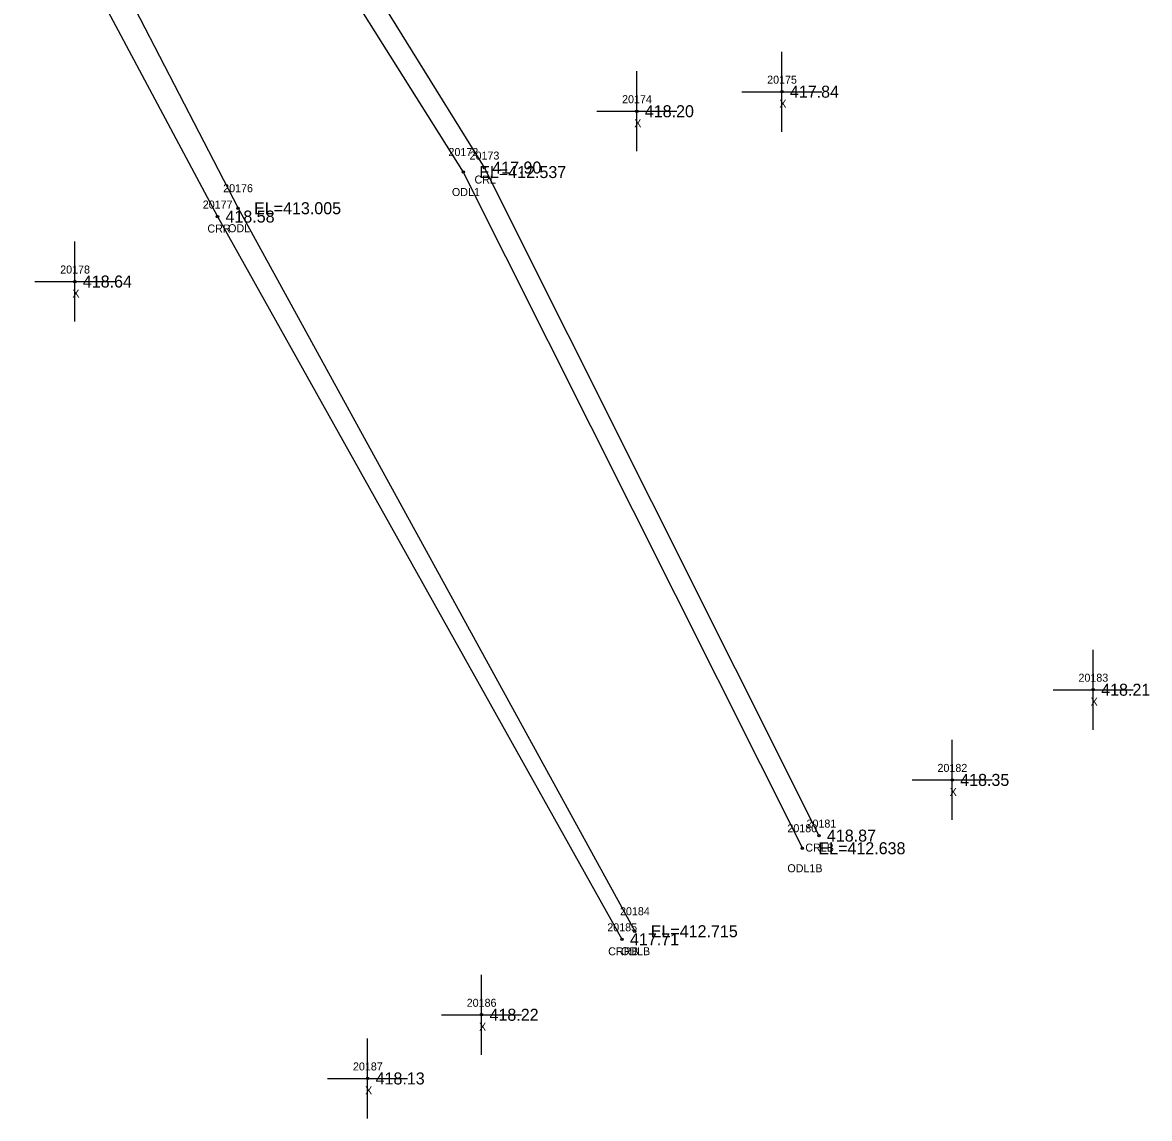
# Model space of a CAD drawing. Extents: x 1613184 to 1614731, y 770859 to 771868.
# Drawn here: x 1614039.7 to 1614180.6, y 770858.6 to 770995.6 of the extents above; entities that cross this region are included whole.
import ezdxf

# ---------------------------------------------------------------- set-up
doc = ezdxf.new("R2010")
doc.units = 0
for name, color, linetype in [('RD_EX_H2O', 7, 'Continuous'), ('RD_EX_H2O_txCode', 7, 'Continuous'), ('RD_EX_Misc', 7, 'Continuous'), ('RD_EX_Misc_txCode', 7, 'Continuous'), ('RD_EX_TX_H2O_ELEV', 7, 'Continuous'), ('RD_EX_TX_Misc_ELEV', 7, 'Continuous'), ('RD_SMD_Locator', 7, 'Continuous')]:
    doc.layers.add(name, color=color, linetype=linetype)

msp = doc.modelspace()

# ---------------------------------------------------------------- linework, layer by layer
at = {"layer": 'RD_EX_H2O'}
for points in [[(1613914.71, 771327.05), (1613912.94, 771270.2), (1613909.29, 771229.14), (1613936.32, 771173.24), (1613961.59, 771155.78), (1613976.99, 771153.11), (1613987.89, 771138.66), (1614016.07, 771061.15), (1614064.07, 770971.34), (1614114.62, 770881.02)], [(1613918.3, 771327.47), (1613915.56, 771269.65), (1613912.54, 771229.9), (1613937.35, 771175.56), (1613962.55, 771156.92), (1613978.15, 771155.33), (1613989.65, 771139.95), (1614019.92, 771062.64), (1614066.64, 770972.38), (1614116.22, 770882.03)], [(1613939.34, 771325.64), (1613936.19, 771267.33), (1613931.54, 771235.48), (1613951.01, 771188.77), (1613971.87, 771179.88), (1613985.53, 771176.18), (1614010.21, 771154.12), (1614036.29, 771069.78), (1614094.78, 770976.9), (1614137.18, 770892.4)], [(1613940.63, 771325.49), (1613938.42, 771267.33), (1613934.3, 771235.92), (1613956.7, 771194.52), (1613973.34, 771185.91), (1613987.6, 771179.19), (1614011.07, 771155.33), (1614038.76, 771071.93), (1614097.41, 770977.46), (1614139.24, 770893.98)]]:
    msp.add_lwpolyline(points, dxfattribs=at)
at = {"layer": 'RD_EX_Misc'}
for p, q in [((1614134.61, 770981.94), (1614134.61, 770991.94)), ((1614116.48, 770979.5), (1614116.48, 770989.5)), ((1614129.61, 770986.94), (1614139.61, 770986.94)), ((1614111.48, 770984.5), (1614121.48, 770984.5)), ((1614046.24, 770958.22), (1614046.24, 770968.22)), ((1614041.24, 770963.22), (1614051.24, 770963.22)), ((1614173.52, 770907.21), (1614173.52, 770917.21)), ((1614168.52, 770912.21), (1614178.52, 770912.21)), ((1614155.9, 770895.94), (1614155.9, 770905.94)), ((1614150.9, 770900.94), (1614160.9, 770900.94)), ((1614097.07, 770866.59), (1614097.07, 770876.59)), ((1614092.07, 770871.59), (1614102.07, 770871.59)), ((1614082.83, 770858.63), (1614082.83, 770868.63)), ((1614077.83, 770863.63), (1614087.83, 770863.63))]:
    msp.add_line(p, q, dxfattribs=at)
at = {"layer": 'RD_SMD_Locator'}
for centre in [(1614134.61, 770986.94), (1614116.48, 770984.5), (1614094.78, 770976.9), (1614097.41, 770977.46), (1614064.07, 770971.34), (1614066.64, 770972.38), (1614046.24, 770963.22), (1614173.52, 770912.21), (1614155.9, 770900.94), (1614139.24, 770893.98), (1614137.18, 770892.4), (1614116.22, 770882.03), (1614114.62, 770881.02), (1614097.07, 770871.59), (1614082.83, 770863.63)]:
    msp.add_circle(centre, 0.15, dxfattribs=at)

# ---------------------------------------------------------------- texts
at = {"layer": 'RD_EX_H2O_txCode'}
for s, p in [('20172', (1614092.94, 770978.9)), ('20173', (1614095.58, 770978.46)), ('CRL', (1614096.19, 770975.46)), ('20176', (1614064.78, 770974.38)), ('ODL1', (1614093.37, 770973.9)), ('20177', (1614062.23, 770972.34)), ('CRR', (1614062.81, 770969.34)), ('ODL', (1614065.4, 770969.38)), ('20180', (1614135.3, 770894.4)), ('20181', (1614137.69, 770894.98)), ('CRLB', (1614137.54, 770891.98)), ('ODL1B', (1614135.3, 770889.4)), ('20184', (1614114.38, 770884.03)), ('20185', (1614112.79, 770882.02)), ('CRRB', (1614112.9, 770879.02)), ('ODLB', (1614114.5, 770879.03))]:
    msp.add_text(s, height=1, dxfattribs=at).set_placement(p)
at = {"layer": 'RD_EX_Misc_txCode'}
for s, p in [('20175', (1614132.77, 770987.94)), ('20174', (1614114.64, 770985.5)), ('X', (1614134.29, 770984.94)), ('X', (1614116.16, 770982.5)), ('20178', (1614044.41, 770964.22)), ('X', (1614045.93, 770961.22)), ('20183', (1614171.68, 770913.21)), ('X', (1614173.2, 770910.21)), ('20182', (1614154.06, 770901.94)), ('X', (1614155.58, 770898.94)), ('20186', (1614095.22, 770872.59)), ('X', (1614096.76, 770869.59)), ('20187', (1614081, 770864.63)), ('X', (1614082.52, 770861.63))]:
    msp.add_text(s, height=1, dxfattribs=at).set_placement(p)
at = {"layer": 'RD_EX_TX_H2O_ELEV'}
for s, p in [('EL=412.537', (1614096.78, 770976.15)), ('417.90', (1614098.41, 770976.71)), ('EL=413.005', (1614068.64, 770971.63)), ('418.58', (1614065.07, 770970.59)), ('418.87', (1614140.24, 770893.23)), ('EL=412.638', (1614139.18, 770891.65)), ('EL=412.715', (1614118.22, 770881.28)), ('417.71', (1614115.62, 770880.27))]:
    msp.add_text(s, height=1.5, dxfattribs=at).set_placement(p)
at = {"layer": 'RD_EX_TX_Misc_ELEV'}
for s, p in [('417.84', (1614135.61, 770986.19)), ('418.20', (1614117.48, 770983.75)), ('418.64', (1614047.24, 770962.47)), ('418.21', (1614174.52, 770911.46)), ('418.35', (1614156.9, 770900.19)), ('418.22', (1614098.07, 770870.84)), ('418.13', (1614083.83, 770862.88))]:
    msp.add_text(s, height=1.5, dxfattribs=at).set_placement(p)

doc.saveas('drawing.dxf')
